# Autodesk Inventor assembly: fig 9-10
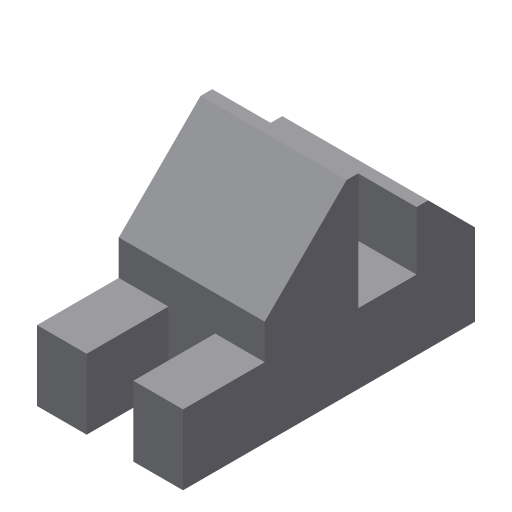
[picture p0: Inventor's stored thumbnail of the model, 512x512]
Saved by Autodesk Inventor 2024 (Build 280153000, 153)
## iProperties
Shininess: 64.0
Length Units: 11269
Angle Units: 11279
Time Units: 11290
Mass Units: 11283
Length Display Precision: 3
Angle Display Precision: 2
Created: 2002-01
Part Number: fig 9-10
Document SubType Name: Assembly
Designer: ***
Density: 0.0
Volumn: 0.0
Area: 0.0
PropertySet Name: Model Information
Control State: 0
Master: False
Checked Out: False
Author: ***
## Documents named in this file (3)
- D:\PROJECTS\Project 2023\RESOURCES INVENTOR 2024\RESOURCES INVENTOR 2024\Inventor_2023_Part\Inventor_2024_Part\c09_Inv_2024_prt\fig 9-10.iam
- D:\PROJECTS\Project 2023\RESOURCES INVENTOR 2024\RESOURCES INVENTOR 2024\Inventor_2023_Part\Inventor_2024_Part\c09_Inv_2024_prt\Part3.ipt
- D:\PROJECTS\Project 2023\RESOURCES INVENTOR 2024\RESOURCES INVENTOR 2024\Inventor_2023_Part\Inventor_2024_Part\c09_Inv_2024_prt\Part4.ipt
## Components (2 placed, 2 different names)
1. Part3:1
2. Part4:1
